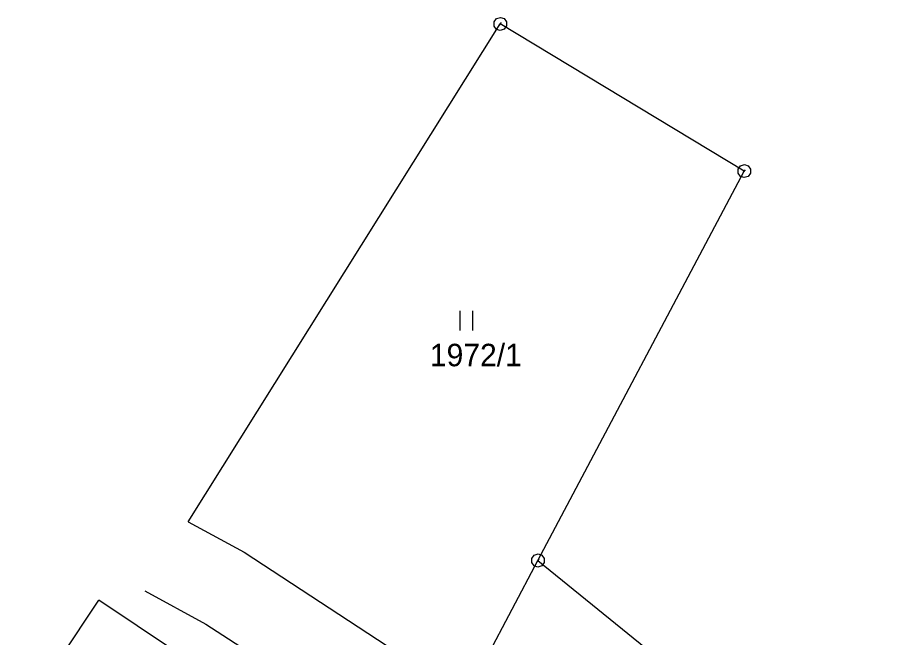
# Model space of a CAD drawing. Extents: x -806774 to -803680, y -1151731 to -1150053.
# Drawn here: x -804103.1 to -804037.4, y -1150099.6 to -1150052.7 of the extents above; entities that cross this region are included whole.
import ezdxf

# ---------------------------------------------------------------- set-up
doc = ezdxf.new("R2010")
doc.units = 0
for name, color, linetype in [('1', 7, 'Continuous'), ('12', 7, 'Continuous'), ('2', 7, 'Continuous'), ('3', 7, 'Continuous'), ('8', 7, 'Continuous')]:
    doc.layers.add(name, color=color, linetype=linetype)

msp = doc.modelspace()

# ---------------------------------------------------------------- linework, layer by layer
at = {"layer": '1'}
for p, q in [((-804090.18, -1150090.88), (-804066.59, -1150053.21)), ((-804048.13, -1150064.34), (-804066.59, -1150053.21)), ((-804063.74, -1150093.81), (-804048.13, -1150064.34)), ((-804090.18, -1150090.88), (-804085.95, -1150093.17)), ((-804085.95, -1150093.17), (-804071.72, -1150102.49)), ((-804069.36, -1150104.41), (-804063.74, -1150093.81)), ((-804063.74, -1150093.81), (-804037.36, -1150115.15)), ((-804093.47, -1150096.1), (-804088.85, -1150098.62)), ((-804103.11, -1150106.05), (-804096.96, -1150096.81)), ((-804091.16, -1150100.68), (-804096.96, -1150096.81)), ((-804088.85, -1150098.62), (-804077.01, -1150106.29))]:
    msp.add_line(p, q, dxfattribs=at)
at = {"layer": '12'}
for p in [(-804103.11, -1150106.05), (-804103.11, -1150106.05), (-804091.16, -1150100.68)]:
    msp.add_line(p, (-804096.96, -1150096.81), dxfattribs=at)
at = {"layer": '3'}
for p, q in [((-804069.65, -1150074.91), (-804069.65, -1150076.41)), ((-804068.65, -1150076.41), (-804068.65, -1150074.91))]:
    msp.add_line(p, q, dxfattribs=at)
at = {"layer": '8'}
for p, q in [((-804066.519, -1150053.113), (-804066.661, -1150053.307)), ((-804048.059, -1150064.243), (-804048.201, -1150064.437)), ((-804063.669, -1150093.713), (-804063.811, -1150093.907))]:
    msp.add_line(p, q, dxfattribs=at)
for points in [[(-804066.292, -1150053.615), (-804066.585, -1150053.71), (-804066.878, -1150053.619), (-804067.052, -1150053.367), (-804067.05, -1150053.059), (-804066.866, -1150052.809), (-804066.573, -1150052.714), (-804066.28, -1150052.805), (-804066.106, -1150053.057), (-804066.108, -1150053.365)], [(-804047.832, -1150064.745), (-804048.125, -1150064.84), (-804048.418, -1150064.749), (-804048.592, -1150064.497), (-804048.59, -1150064.189), (-804048.406, -1150063.939), (-804048.113, -1150063.844), (-804047.82, -1150063.935), (-804047.646, -1150064.187), (-804047.648, -1150064.495)], [(-804063.442, -1150094.215), (-804063.735, -1150094.31), (-804064.028, -1150094.219), (-804064.202, -1150093.967), (-804064.2, -1150093.659), (-804064.016, -1150093.409), (-804063.723, -1150093.314), (-804063.43, -1150093.405), (-804063.256, -1150093.657), (-804063.258, -1150093.965)]]:
    msp.add_lwpolyline(points, close=True, dxfattribs=at)

# ---------------------------------------------------------------- texts
at = {"layer": '2'}
msp.add_text('1972/1', height=1.7, dxfattribs=at).set_placement((-804071.907, -1150079.11))

doc.saveas('drawing.dxf')
